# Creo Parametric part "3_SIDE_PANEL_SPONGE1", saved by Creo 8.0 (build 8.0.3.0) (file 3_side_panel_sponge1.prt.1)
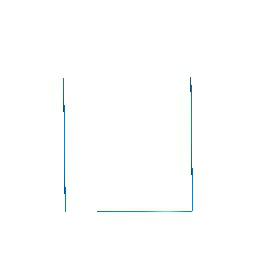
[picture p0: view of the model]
Units: millimeter Newton Second (mmNs); MM, TONNE, SECS

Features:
  1. datum plane "DTM1"
  2. datum plane "DTM2"
  3. datum plane "DTM3"
  4. coordinate system
  5. datum plane "DTM4"
  6. datum plane "DTM5"
  7. curve
  8. protrusion

Other named items: CS0

Layers: 0_ALL_AXIS, 0_ALL_CSYS, 0_ALL_CURVES, 0_ALL_PLANES, 0_ALL_POINTS, 0_ALL_SURFS, 3_SIDE_PANEL_SPONGE1

Surfaces: 3 plane, 3 cylinder, 2 torus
